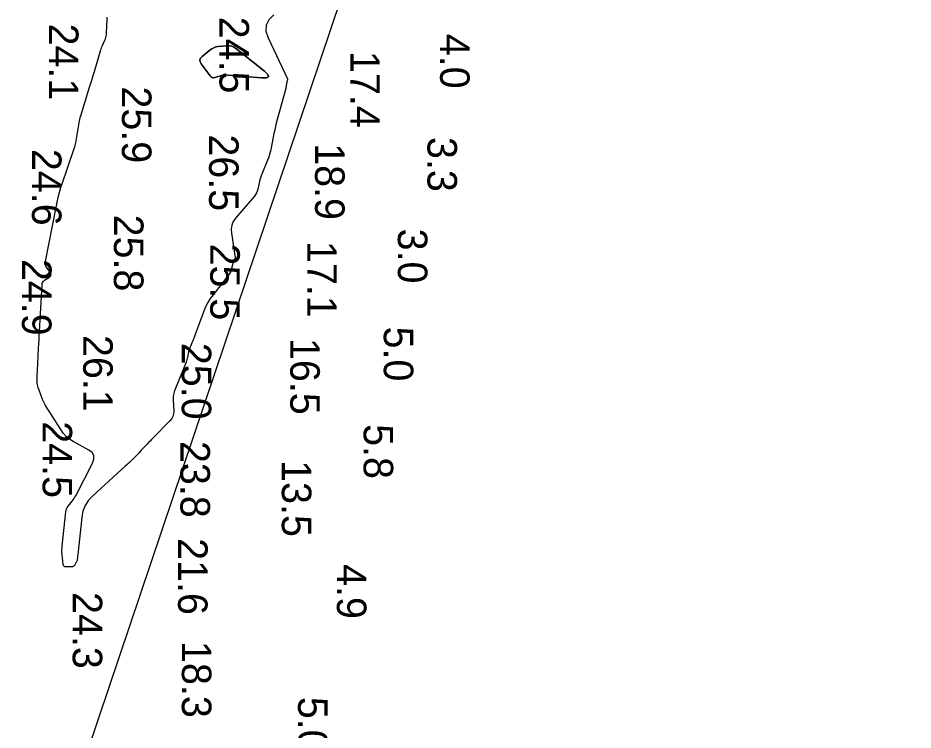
# Model space of a CAD drawing. Extents: x 1178573 to 1187098, y 693282 to 751751.
# Drawn here: x 1186460.8 to 1186839.9, y 727582.7 to 727884.4 of the extents above; entities that cross this region are included whole.
import ezdxf

# ---------------------------------------------------------------- set-up
doc = ezdxf.new("R2010")
doc.units = 0
for name, color, linetype in [('G-ANNO-PATT', 7, 'Continuous'), ('V-HYDS-MAJR', 7, 'Continuous'), ('V-HYDS-SOUN', 7, 'Continuous')]:
    doc.layers.add(name, color=color, linetype=linetype)

msp = doc.modelspace()

# ---------------------------------------------------------------- linework, layer by layer
at = {"layer": 'G-ANNO-PATT'}
for p, q in [((1186337.91, 727120.31), (1186839.88, 728613.33)), ((1186498.5, 727882.85), (1186498.56, 727883.81)), ((1186498.56, 727883.81), (1186498.63, 727884.78)), ((1186567.02, 727883.66), (1186565.91, 727881.34)), ((1186569.14, 727885.72), (1186567.02, 727883.66)), ((1186498.21, 727877.31), (1186498.44, 727881.88)), ((1186498.44, 727881.88), (1186498.5, 727882.85)), ((1186565.91, 727881.34), (1186565.79, 727878.78)), ((1186497.86, 727875.54), (1186498.03, 727876.12)), ((1186498.03, 727876.12), (1186498.15, 727876.71)), ((1186498.15, 727876.71), (1186498.21, 727877.31)), ((1186565.79, 727878.78), (1186566.68, 727875.96)), ((1186566.68, 727875.96), (1186574.87, 727858.57)), ((1186496.14, 727871.63), (1186496.37, 727872.2)), ((1186496.37, 727872.2), (1186496.61, 727872.76)), ((1186496.61, 727872.76), (1186497.63, 727874.98)), ((1186497.63, 727874.98), (1186497.86, 727875.54)), ((1186493.14, 727861.74), (1186495.75, 727870.47)), ((1186495.75, 727870.47), (1186495.93, 727871.05)), ((1186495.93, 727871.05), (1186496.14, 727871.63)), ((1186492.64, 727860.09), (1186493.14, 727861.74)), ((1186491.14, 727855.14), (1186491.64, 727856.79)), ((1186491.64, 727856.79), (1186492.14, 727858.44)), ((1186492.14, 727858.44), (1186492.64, 727860.09)), ((1186574.57, 727856.84), (1186574.38, 727855.56)), ((1186574.59, 727856.99), (1186574.57, 727856.84)), ((1186574.62, 727857.14), (1186574.59, 727856.99)), ((1186574.66, 727857.29), (1186574.62, 727857.14)), ((1186574.71, 727857.43), (1186574.66, 727857.29)), ((1186574.9, 727858.01), (1186574.71, 727857.43)), ((1186574.87, 727858.57), (1186574.92, 727858.43)), ((1186574.94, 727858.15), (1186574.9, 727858.01)), ((1186574.92, 727858.43), (1186574.94, 727858.29)), ((1186574.94, 727858.29), (1186574.94, 727858.15)), ((1186487.39, 727842.95), (1186491.14, 727855.14)), ((1186574.16, 727854.52), (1186570.56, 727841.33)), ((1186574.23, 727854.78), (1186574.16, 727854.52)), ((1186574.29, 727855.04), (1186574.23, 727854.78)), ((1186574.34, 727855.3), (1186574.29, 727855.04)), ((1186574.38, 727855.56), (1186574.34, 727855.3)), ((1186486.99, 727841.44), (1186487.18, 727842.2)), ((1186487.18, 727842.2), (1186487.39, 727842.95)), ((1186486.13, 727836.52), (1186486.68, 727839.91)), ((1186486.68, 727839.91), (1186486.82, 727840.68)), ((1186486.82, 727840.68), (1186486.99, 727841.44)), ((1186569.82, 727838.43), (1186569.5, 727836.97)), ((1186570.18, 727839.88), (1186569.82, 727838.43)), ((1186570.56, 727841.33), (1186570.18, 727839.88)), ((1186485.26, 727831.57), (1186485.7, 727834.04)), ((1186485.7, 727834.04), (1186485.81, 727834.66)), ((1186485.81, 727834.66), (1186485.92, 727835.28)), ((1186485.92, 727835.28), (1186486.03, 727835.9)), ((1186486.03, 727835.9), (1186486.13, 727836.52)), ((1186569.2, 727835.5), (1186568.01, 727829.33)), ((1186569.5, 727836.97), (1186569.2, 727835.5)), ((1186484.82, 727829.74), (1186484.99, 727830.35)), ((1186484.99, 727830.35), (1186485.13, 727830.96)), ((1186485.13, 727830.96), (1186485.26, 727831.57)), ((1186479.33, 727813.73), (1186484.62, 727829.15)), ((1186484.62, 727829.15), (1186484.82, 727829.74)), ((1186567.37, 727826.72), (1186566.96, 727825.45)), ((1186567.72, 727828.02), (1186567.37, 727826.72)), ((1186568.01, 727829.33), (1186567.72, 727828.02)), ((1186566.48, 727824.19), (1186564.07, 727818.25)), ((1186566.96, 727825.45), (1186566.48, 727824.19)), ((1186563.08, 727815.08), (1186562.35, 727811.84)), ((1186563.27, 727815.89), (1186563.08, 727815.08)), ((1186563.5, 727816.69), (1186563.27, 727815.89)), ((1186563.77, 727817.47), (1186563.5, 727816.69)), ((1186564.07, 727818.25), (1186563.77, 727817.47)), ((1186478.5, 727811.03), (1186478.95, 727812.57)), ((1186478.95, 727812.57), (1186479.04, 727812.86)), ((1186479.04, 727812.86), (1186479.13, 727813.15)), ((1186479.13, 727813.15), (1186479.23, 727813.44)), ((1186479.23, 727813.44), (1186479.33, 727813.73)), ((1186562.35, 727811.84), (1186562.12, 727811.05)), ((1186477.51, 727806.92), (1186478.15, 727809.66)), ((1186478.15, 727809.66), (1186478.18, 727809.78)), ((1186478.18, 727809.78), (1186478.2, 727809.89)), ((1186478.2, 727809.89), (1186478.23, 727810.01)), ((1186478.23, 727810.01), (1186478.26, 727810.12)), ((1186478.26, 727810.12), (1186478.37, 727810.58)), ((1186478.37, 727810.58), (1186478.4, 727810.69)), ((1186478.4, 727810.69), (1186478.43, 727810.81)), ((1186478.43, 727810.81), (1186478.46, 727810.92)), ((1186478.46, 727810.92), (1186478.5, 727811.03)), ((1186560.91, 727808.95), (1186552.96, 727799.55)), ((1186561.4, 727809.6), (1186560.91, 727808.95)), ((1186561.81, 727810.31), (1186561.4, 727809.6)), ((1186562.12, 727811.05), (1186561.81, 727810.31)), ((1186472.45, 727781.21), (1186477.08, 727804.93)), ((1186477.08, 727804.93), (1186477.18, 727805.43)), ((1186477.18, 727805.43), (1186477.28, 727805.93)), ((1186477.28, 727805.93), (1186477.39, 727806.42)), ((1186477.39, 727806.42), (1186477.51, 727806.92)), ((1186551.34, 727796.59), (1186551.07, 727794.95)), ((1186551.97, 727798.12), (1186551.34, 727796.59)), ((1186552.96, 727799.55), (1186551.97, 727798.12)), ((1186551.07, 727794.95), (1186551.16, 727793.22)), ((1186551.16, 727793.22), (1186552.7, 727782.97)), ((1186472.38, 727780.55), (1186472.45, 727781.21)), ((1186551.89, 727780.83), (1186551.81, 727780.61)), ((1186551.98, 727781.04), (1186551.89, 727780.83)), ((1186552.09, 727781.25), (1186551.98, 727781.04)), ((1186552.54, 727782.08), (1186552.09, 727781.25)), ((1186552.63, 727782.29), (1186552.54, 727782.08)), ((1186552.69, 727782.51), (1186552.63, 727782.29)), ((1186552.71, 727782.73), (1186552.69, 727782.51)), ((1186552.7, 727782.97), (1186552.71, 727782.73)), ((1186472.44, 727779.92), (1186472.38, 727780.55)), ((1186472.63, 727779.31), (1186472.44, 727779.92)), ((1186472.94, 727778.73), (1186472.63, 727779.31)), ((1186474.53, 727776.35), (1186472.94, 727778.73)), ((1186550.98, 727777.22), (1186550.78, 727776.74)), ((1186551.13, 727777.73), (1186550.98, 727777.22)), ((1186551.75, 727780.38), (1186551.13, 727777.73)), ((1186551.81, 727780.61), (1186551.75, 727780.38)), ((1186471.64, 727772.94), (1186472.09, 727773.31)), ((1186472.09, 727773.31), (1186474.17, 727774.65)), ((1186474.17, 727774.65), (1186474.58, 727775.01)), ((1186474.76, 727775.86), (1186474.53, 727776.35)), ((1186474.58, 727775.01), (1186474.78, 727775.41)), ((1186474.78, 727775.41), (1186474.76, 727775.86)), ((1186550.23, 727775.85), (1186543.4, 727767.14)), ((1186550.53, 727776.28), (1186550.23, 727775.85)), ((1186550.78, 727776.74), (1186550.53, 727776.28)), ((1186469.89, 727751.6), (1186470.99, 727771.4)), ((1186470.99, 727771.4), (1186471.08, 727771.99)), ((1186471.08, 727771.99), (1186471.3, 727772.5)), ((1186471.3, 727772.5), (1186471.64, 727772.94)), ((1186543.4, 727767.14), (1186542.22, 727765.51)), ((1186540.27, 727762.03), (1186539.5, 727760.17)), ((1186541.17, 727763.81), (1186540.27, 727762.03)), ((1186542.22, 727765.51), (1186541.17, 727763.81)), ((1186539.5, 727760.17), (1186535.44, 727749.14)), ((1186469.79, 727749.81), (1186469.89, 727751.6)), ((1186469.6, 727746.24), (1186469.7, 727748.02)), ((1186469.7, 727748.02), (1186469.79, 727749.81)), ((1186534.61, 727747.06), (1186533.72, 727744.99)), ((1186534.83, 727747.57), (1186534.61, 727747.06)), ((1186535.04, 727748.09), (1186534.83, 727747.57)), ((1186535.25, 727748.61), (1186535.04, 727748.09)), ((1186535.44, 727749.14), (1186535.25, 727748.61)), ((1186469.03, 727734.91), (1186469.51, 727744.45)), ((1186469.51, 727744.45), (1186469.6, 727746.24)), ((1186533.18, 727743.43), (1186533.05, 727742.89)), ((1186533.34, 727743.95), (1186533.18, 727743.43)), ((1186533.52, 727744.47), (1186533.34, 727743.95)), ((1186533.72, 727744.99), (1186533.52, 727744.47)), ((1186532.14, 727739.13), (1186531.95, 727738.62)), ((1186532.31, 727739.66), (1186532.14, 727739.13)), ((1186532.46, 727740.19), (1186532.31, 727739.66)), ((1186532.59, 727740.73), (1186532.46, 727740.19)), ((1186533.05, 727742.89), (1186532.59, 727740.73)), ((1186531.95, 727738.62), (1186527.34, 727727.07)), ((1186468.93, 727730.14), (1186468.96, 727732.53)), ((1186468.96, 727732.53), (1186468.97, 727733.12)), ((1186468.97, 727733.12), (1186468.98, 727733.72)), ((1186468.98, 727733.72), (1186469, 727734.32)), ((1186469, 727734.32), (1186469.03, 727734.91)), ((1186468.95, 727729.54), (1186468.93, 727730.14)), ((1186469.03, 727728.96), (1186468.95, 727729.54)), ((1186469.15, 727728.38), (1186469.03, 727728.96)), ((1186469.33, 727727.82), (1186469.15, 727728.38)), ((1186470.86, 727723.58), (1186469.33, 727727.82)), ((1186526.71, 727724.84), (1186526.57, 727723.69)), ((1186526.96, 727725.97), (1186526.71, 727724.84)), ((1186527.34, 727727.07), (1186526.96, 727725.97)), ((1186471.21, 727722.7), (1186470.86, 727723.58)), ((1186471.6, 727721.84), (1186471.21, 727722.7)), ((1186472.03, 727721), (1186471.6, 727721.84)), ((1186472.51, 727720.19), (1186472.03, 727721)), ((1186478.89, 727709.98), (1186472.51, 727720.19)), ((1186526.57, 727723.69), (1186526.55, 727722.52)), ((1186526.55, 727722.52), (1186526.73, 727717.8)), ((1186526.67, 727716.66), (1186526.38, 727715.61)), ((1186526.73, 727717.8), (1186526.67, 727716.66)), ((1186525.17, 727713.75), (1186517.95, 727706.38)), ((1186525.88, 727714.64), (1186525.17, 727713.75)), ((1186526.38, 727715.61), (1186525.88, 727714.64)), ((1186479.98, 727708.46), (1186478.89, 727709.98)), ((1186481.23, 727707.11), (1186479.98, 727708.46)), ((1186482.64, 727705.93), (1186481.23, 727707.11)), ((1186484.21, 727704.93), (1186482.64, 727705.93)), ((1186516.74, 727705.13), (1186516.13, 727704.5)), ((1186517.35, 727705.76), (1186516.74, 727705.13)), ((1186517.95, 727706.38), (1186517.35, 727705.76)), ((1186490.84, 727701.25), (1186484.21, 727704.93)), ((1186492.19, 727700.24), (1186490.84, 727701.25)), ((1186513.03, 727701.23), (1186512.47, 727700.65)), ((1186515.53, 727703.87), (1186513.03, 727701.23)), ((1186516.13, 727704.5), (1186515.53, 727703.87)), ((1186492.9, 727699.03), (1186492.19, 727700.24)), ((1186492.44, 727696.04), (1186492.98, 727697.63)), ((1186492.98, 727697.63), (1186492.9, 727699.03)), ((1186510.79, 727698.93), (1186508.52, 727696.65)), ((1186511.35, 727699.5), (1186510.79, 727698.93)), ((1186511.92, 727700.07), (1186511.35, 727699.5)), ((1186512.47, 727700.65), (1186511.92, 727700.07)), ((1186485.26, 727681.94), (1186492.44, 727696.04)), ((1186506.2, 727694.43), (1186492.45, 727681.98)), ((1186506.79, 727694.98), (1186506.2, 727694.43)), ((1186507.37, 727695.53), (1186506.79, 727694.98)), ((1186507.95, 727696.09), (1186507.37, 727695.53)), ((1186508.52, 727696.65), (1186507.95, 727696.09)), ((1186482.05, 727677.53), (1186483.78, 727679.66)), ((1186483.78, 727679.66), (1186484.19, 727680.2)), ((1186484.19, 727680.2), (1186484.58, 727680.76)), ((1186484.58, 727680.76), (1186484.93, 727681.34)), ((1186484.93, 727681.34), (1186485.26, 727681.94)), ((1186490.63, 727680.03), (1186489.25, 727677.85)), ((1186492.45, 727681.98), (1186490.63, 727680.03)), ((1186479.51, 727660.66), (1186481.04, 727675.1)), ((1186481.04, 727675.1), (1186481.16, 727675.76)), ((1186481.16, 727675.76), (1186481.37, 727676.39)), ((1186481.37, 727676.39), (1186481.66, 727676.97)), ((1186481.66, 727676.97), (1186482.05, 727677.53)), ((1186488.3, 727675.45), (1186487.79, 727672.83)), ((1186489.25, 727677.85), (1186488.3, 727675.45)), ((1186487.79, 727672.83), (1186486.11, 727656.99)), ((1186479.41, 727658.89), (1186479.44, 727659.78)), ((1186479.44, 727659.78), (1186479.51, 727660.66)), ((1186479.43, 727658), (1186479.41, 727658.89)), ((1186479.49, 727657.11), (1186479.43, 727658)), ((1186479.89, 727652.86), (1186479.49, 727657.11)), ((1186485.99, 727655.89), (1186485.86, 727654.78)), ((1186486.02, 727656.16), (1186485.99, 727655.89)), ((1186486.05, 727656.44), (1186486.02, 727656.16)), ((1186486.08, 727656.72), (1186486.05, 727656.44)), ((1186486.11, 727656.99), (1186486.08, 727656.72)), ((1186480.01, 727652.39), (1186479.89, 727652.86)), ((1186480.24, 727652.06), (1186480.01, 727652.39)), ((1186480.6, 727651.86), (1186480.24, 727652.06)), ((1186484.23, 727652.02), (1186483.94, 727651.9)), ((1186484.47, 727652.21), (1186484.23, 727652.02)), ((1186484.68, 727652.46), (1186484.47, 727652.21)), ((1186485.49, 727653.76), (1186484.68, 727652.46)), ((1186485.63, 727654), (1186485.49, 727653.76)), ((1186485.73, 727654.25), (1186485.63, 727654)), ((1186485.81, 727654.51), (1186485.73, 727654.25)), ((1186485.86, 727654.78), (1186485.81, 727654.51)), ((1186481.07, 727651.81), (1186480.6, 727651.86)), ((1186483.61, 727651.86), (1186481.07, 727651.81)), ((1186483.94, 727651.9), (1186483.61, 727651.86))]:
    msp.add_line(p, q, dxfattribs=at)
msp.add_lwpolyline([(1186548.99, 727860.27), (1186549.68, 727860.24), (1186564, 727859), (1186566.04, 727859), (1186566.91, 727859.47), (1186566.6, 727860.41), (1186565.13, 727861.82), (1186552.93, 727871.56), (1186552.14, 727872.08), (1186551.3, 727872.43), (1186550.41, 727872.61), (1186549.46, 727872.61), (1186545.58, 727872.26), (1186544.63, 727872.11), (1186543.74, 727871.82), (1186542.91, 727871.4), (1186542.13, 727870.84), (1186538.76, 727868.05), (1186538.13, 727867.36), (1186537.85, 727866.62), (1186537.94, 727865.84), (1186538.38, 727865.01), (1186542.13, 727859.91), (1186542.57, 727859.44), (1186543.08, 727859.17), (1186543.65, 727859.08), (1186544.29, 727859.18), (1186546.96, 727859.97), (1186547.63, 727860.14), (1186548.31, 727860.24), (1186548.99, 727860.27)], dxfattribs=at)
at = {"layer": 'V-HYDS-MAJR'}
msp.add_lwpolyline([(1186569.14, 727885.72), (1186567.02, 727883.66), (1186565.91, 727881.34), (1186565.79, 727878.78), (1186566.68, 727875.96), (1186574.87, 727858.57), (1186574.92, 727858.43), (1186574.94, 727858.29), (1186574.94, 727858.15), (1186574.9, 727858.01), (1186574.71, 727857.43), (1186574.66, 727857.29), (1186574.62, 727857.14), (1186574.59, 727856.99), (1186574.57, 727856.84), (1186574.38, 727855.56), (1186574.34, 727855.3), (1186574.29, 727855.04), (1186574.23, 727854.78), (1186574.16, 727854.52), (1186570.56, 727841.33), (1186570.18, 727839.88), (1186569.82, 727838.43), (1186569.5, 727836.97), (1186569.2, 727835.5), (1186568.01, 727829.33), (1186567.72, 727828.02), (1186567.37, 727826.72), (1186566.96, 727825.45), (1186566.48, 727824.19), (1186564.07, 727818.25), (1186563.77, 727817.47), (1186563.5, 727816.69), (1186563.27, 727815.89), (1186563.08, 727815.08), (1186562.35, 727811.84), (1186562.12, 727811.05), (1186561.81, 727810.31), (1186561.4, 727809.6), (1186560.91, 727808.95), (1186552.96, 727799.55), (1186551.97, 727798.12), (1186551.34, 727796.59), (1186551.07, 727794.95), (1186551.16, 727793.22), (1186552.7, 727782.97), (1186552.71, 727782.73), (1186552.69, 727782.51), (1186552.63, 727782.29), (1186552.54, 727782.08), (1186552.09, 727781.25), (1186551.98, 727781.04), (1186551.89, 727780.83), (1186551.81, 727780.61), (1186551.75, 727780.38), (1186551.13, 727777.73), (1186550.98, 727777.22), (1186550.78, 727776.74), (1186550.53, 727776.28), (1186550.23, 727775.85), (1186543.4, 727767.14), (1186542.22, 727765.51), (1186541.17, 727763.81), (1186540.27, 727762.03), (1186539.5, 727760.17), (1186535.44, 727749.14), (1186535.25, 727748.61), (1186535.04, 727748.09), (1186534.83, 727747.57), (1186534.61, 727747.06), (1186533.72, 727744.99), (1186533.52, 727744.47), (1186533.34, 727743.95), (1186533.18, 727743.43), (1186533.05, 727742.89), (1186532.59, 727740.73), (1186532.46, 727740.19), (1186532.31, 727739.66), (1186532.14, 727739.13), (1186531.95, 727738.62), (1186527.34, 727727.07), (1186526.96, 727725.97), (1186526.71, 727724.84), (1186526.57, 727723.69), (1186526.55, 727722.52), (1186526.73, 727717.8), (1186526.67, 727716.66), (1186526.38, 727715.61), (1186525.88, 727714.64), (1186525.17, 727713.75), (1186517.95, 727706.38), (1186517.35, 727705.76), (1186516.74, 727705.13), (1186516.13, 727704.5), (1186515.53, 727703.87), (1186513.03, 727701.23), (1186512.47, 727700.65), (1186511.92, 727700.07), (1186511.35, 727699.5), (1186510.79, 727698.93), (1186508.52, 727696.65), (1186507.95, 727696.09), (1186507.37, 727695.53), (1186506.79, 727694.98), (1186506.2, 727694.43), (1186492.45, 727681.98), (1186490.63, 727680.03), (1186489.25, 727677.85), (1186488.3, 727675.45), (1186487.79, 727672.83), (1186486.11, 727656.99), (1186486.08, 727656.72), (1186486.05, 727656.44), (1186486.02, 727656.16), (1186485.99, 727655.89), (1186485.86, 727654.78), (1186485.81, 727654.51), (1186485.73, 727654.25), (1186485.63, 727654), (1186485.49, 727653.76), (1186484.68, 727652.46), (1186484.47, 727652.21), (1186484.23, 727652.02), (1186483.94, 727651.9), (1186483.61, 727651.86), (1186481.07, 727651.81), (1186480.6, 727651.86), (1186480.24, 727652.06), (1186480.01, 727652.39), (1186479.89, 727652.86), (1186479.49, 727657.11), (1186479.43, 727658), (1186479.41, 727658.89), (1186479.44, 727659.78), (1186479.51, 727660.66), (1186481.04, 727675.1), (1186481.16, 727675.76), (1186481.37, 727676.39), (1186481.66, 727676.97), (1186482.05, 727677.53), (1186483.78, 727679.66), (1186484.19, 727680.2), (1186484.58, 727680.76), (1186484.93, 727681.34), (1186485.26, 727681.94), (1186492.44, 727696.04), (1186492.98, 727697.63), (1186492.9, 727699.03), (1186492.19, 727700.24), (1186490.84, 727701.25), (1186484.21, 727704.93), (1186482.64, 727705.93), (1186481.23, 727707.11), (1186479.98, 727708.46), (1186478.89, 727709.98), (1186472.51, 727720.19), (1186472.03, 727721), (1186471.6, 727721.84), (1186471.21, 727722.7), (1186470.86, 727723.58), (1186469.33, 727727.82), (1186469.15, 727728.38), (1186469.03, 727728.96), (1186468.95, 727729.54), (1186468.93, 727730.14), (1186468.96, 727732.53), (1186468.97, 727733.12), (1186468.98, 727733.72), (1186469, 727734.32), (1186469.03, 727734.91), (1186469.51, 727744.45), (1186469.6, 727746.24), (1186469.7, 727748.02), (1186469.79, 727749.81), (1186469.89, 727751.6), (1186470.99, 727771.4), (1186471.08, 727771.99), (1186471.3, 727772.5), (1186471.64, 727772.94), (1186472.09, 727773.31), (1186474.17, 727774.65), (1186474.58, 727775.01), (1186474.78, 727775.41), (1186474.76, 727775.86), (1186474.53, 727776.35), (1186472.94, 727778.73), (1186472.63, 727779.31), (1186472.44, 727779.92), (1186472.38, 727780.55), (1186472.45, 727781.21), (1186477.08, 727804.93), (1186477.18, 727805.43), (1186477.28, 727805.93), (1186477.39, 727806.42), (1186477.51, 727806.92), (1186478.15, 727809.66), (1186478.18, 727809.78), (1186478.2, 727809.89), (1186478.23, 727810.01), (1186478.26, 727810.12), (1186478.37, 727810.58), (1186478.4, 727810.69), (1186478.43, 727810.81), (1186478.46, 727810.92), (1186478.5, 727811.03), (1186478.95, 727812.57), (1186479.04, 727812.86), (1186479.13, 727813.15), (1186479.23, 727813.44), (1186479.33, 727813.73), (1186484.62, 727829.15), (1186484.82, 727829.74), (1186484.99, 727830.35), (1186485.13, 727830.96), (1186485.26, 727831.57), (1186485.7, 727834.04), (1186485.81, 727834.66), (1186485.92, 727835.28), (1186486.03, 727835.9), (1186486.13, 727836.52), (1186486.68, 727839.91), (1186486.82, 727840.68), (1186486.99, 727841.44), (1186487.18, 727842.2), (1186487.39, 727842.95), (1186491.14, 727855.14), (1186491.64, 727856.79), (1186492.14, 727858.44), (1186492.64, 727860.09), (1186493.14, 727861.74), (1186495.75, 727870.47), (1186495.93, 727871.05), (1186496.14, 727871.63), (1186496.37, 727872.2), (1186496.61, 727872.76), (1186497.63, 727874.98), (1186497.86, 727875.54), (1186498.03, 727876.12), (1186498.15, 727876.71), (1186498.21, 727877.31), (1186498.44, 727881.88), (1186498.5, 727882.85), (1186498.56, 727883.81), (1186498.63, 727884.78)], dxfattribs=at)
msp.add_lwpolyline([(1186548.31, 727860.24), (1186547.63, 727860.14), (1186546.96, 727859.97), (1186544.29, 727859.18), (1186543.65, 727859.08), (1186543.08, 727859.17), (1186542.57, 727859.44), (1186542.13, 727859.91), (1186538.38, 727865.01), (1186537.94, 727865.84), (1186537.85, 727866.62), (1186538.13, 727867.36), (1186538.76, 727868.05), (1186542.13, 727870.84), (1186542.91, 727871.4), (1186543.74, 727871.82), (1186544.63, 727872.11), (1186545.58, 727872.26), (1186549.46, 727872.61), (1186550.41, 727872.61), (1186551.3, 727872.43), (1186552.14, 727872.08), (1186552.93, 727871.56), (1186565.13, 727861.82), (1186566.6, 727860.41), (1186566.91, 727859.47), (1186566.04, 727859), (1186564, 727859), (1186549.68, 727860.24), (1186548.99, 727860.27)], close=True, dxfattribs=at)

# ---------------------------------------------------------------- texts
at = {"layer": 'V-HYDS-SOUN'}
for s, p in [('24.5 ', (1186546.12, 727884.95)), ('24.1 ', (1186473.91, 727882.04)), ('4.0', (1186639.56, 727877.7)), ('17.4 ', (1186601.53, 727870.42)), ('25.9 ', (1186504.82, 727855.41)), ('26.5 ', (1186541.73, 727835.08)), ('3.3', (1186634.21, 727833.99)), ('24.6 ', (1186466.72, 727828.94)), ('18.9 ', (1186586.61, 727831.36)), ('25.8 ', (1186501.44, 727801.08)), ('3.0', (1186621.68, 727795.15)), ('17.1 ', (1186583.3, 727789.92)), ('25.5 ', (1186542.22, 727788.82)), ('24.9 ', (1186462.49, 727782.32)), ('5.0', (1186615.71, 727753.65)), ('26.1 ', (1186488.42, 727750.09)), ('16.5 ', (1186576.11, 727748.83)), ('25.0 ', (1186530.14, 727746.76)), ('24.5 ', (1186471.22, 727713.53)), ('5.8', (1186607.18, 727712.32)), ('23.8 ', (1186529.59, 727705.18)), ('13.5 ', (1186572.53, 727697.06)), ('21.6 ', (1186528.59, 727664.01)), ('4.9', (1186595.86, 727653)), ('24.3 ', (1186483.97, 727641.17)), ('18.3 ', (1186530.2, 727620.41)), ('5.0', (1186579.42, 727596.76))]:
    msp.add_text(s, height=12.5, rotation=270, dxfattribs=at).set_placement(p)

doc.saveas('drawing.dxf')
